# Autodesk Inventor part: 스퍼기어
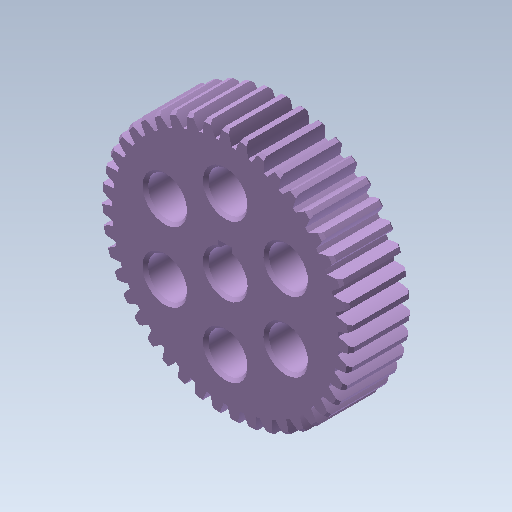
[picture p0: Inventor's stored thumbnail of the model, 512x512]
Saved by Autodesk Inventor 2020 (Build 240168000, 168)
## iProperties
CustomPartVersion: 1
Created: 2010-04
Part Number: 스퍼기어
Material: 강철, 탄소
Document SubType Name: Modeling
Designer: 진현석
Categories: <?xml version="1.0" encoding="UTF-16"?> <MemberInstance><Categories><FamilyTemplate><FamilyTemplateParameter ValueType="xs:double" Id="1" ObjectReferenceKey="da
Density: 1 g/cm^3
Appearance: 기본값(1)
Author: 진현석
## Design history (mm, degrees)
sketch "Sketch1"
  geometry: C1 r 45 at (0, 0)
  constraints: 1 centre point
  dimensions: "d0" = 90 diameter of C1 (= da_da)
extrude "Extrusion1" new body sketch "Sketch1" distance "d1" = 22 (= da_b); taper "d2" = 0 deg
workplane "Work Plane2"
feature "피치 지름" dims "d4" = 10, "d5" = 0
workplane "Work Plane8"
workplane "Work Plane9"
feature "스퍼 기어" dims "d17" = 0, "da_b" = 22, "da_d" = 86, "da_aw" = 129, "da_da" = 90, "da_df" = 81, "da_dw" = 86, angle "da_beta" = 0 deg, "da_lefttooth" = 0, "da_righttooth" = 0
chamfer "모따기1" distance "d49" = 1; stored, may be unused: second distance "d50" = 2, angle "d51" = 45 deg
sketch "스케치3"
  geometry: L1 (-2.5, 9.3)-(2.5, 9.3); L2 (2.5, 9.3)-(2.5, 3.359); L3 (2.5, 3.359)-(-2.5, 3.359); L4 (-2.5, 3.359)-(-2.5, 9.3); C1 r 7 at (0, 0); A1 r 44 centre (0, 0) between (40.958, 16.077) and (40.001, 18.327) reference; A2 r 40.5 centre (0, 0) between (38.563, 12.374) and (38.086, 13.775) reference; 1 further point
  constraints: 8 end point, 2 parallel, 1 centre point, 1 coincident, 1 horizontal, 1 midpoint, 1 perpendicular, 1 vertical alignment
  dimensions: "d52" = 14 diameter of C1; "d53" = 2.3 distance edge to line of C1 L1; "d54" = 5 distance of L1.start L1.end
extrude "돌출2" cut sketch "스케치3" extent not by distance; stored distance "d55" = 10; taper "d56" = 0 deg
sketch "스케치4"
  geometry: C1 r 7 at (0, 25); A1 r 7 centre (0, 0) between (-2.5, 6.538) and (2.5, 6.538) reference; A2 r 40.5 centre (0, 0) between (36.351, 17.857) and (35.674, 19.173) reference
  constraints: 1 centre point, 1 vertical alignment
  dimensions: "d57" = 25 distance of A1.centre C1.centre; "d58" = 14 diameter of C1
extrude "돌출3" cut sketch "스케치4" extent not by distance; stored distance "d59" = 10; taper "d60" = 0 deg
chamfer "모따기2" distance "d65" = 1; stored, may be unused: second distance "d66" = 2, angle "d67" = 45 deg
body "Solid1"
pattern_circular "원형 패턴1" dims angle "d63" = 360 deg
sketch "Sketch2"
  geometry: C1 r 45 at (0, 0) reference; C2 r 43 at (0, 0)
  constraints: 1 centre point, 1 coincident
  dimensions: "d3" = 86 diameter of C2 (= da_dw)
body "Srf1"
other parameters: "d16" = 129 (= da_aw), "d34" = 0.7306 (computed from da_z), "d39" = 0, "d41" = 0, "d43" = 129 (= da_aw), "d46" = 129 (= da_aw), "d47" = 0, "d48" = 0
